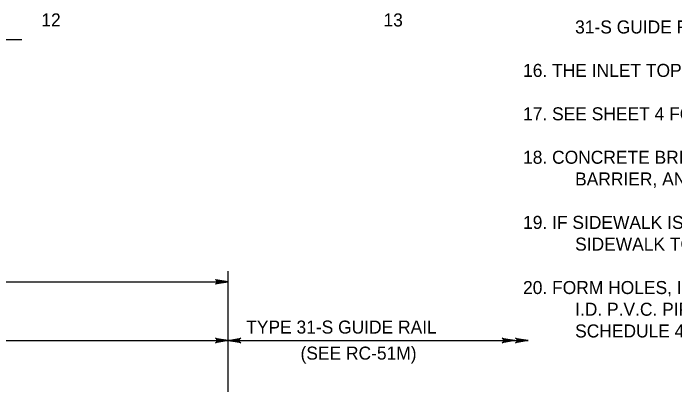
# Model space of a CAD drawing. Extents: x 632007860 to 635435983, y 295418622 to 297794622.
# Drawn here: x 632482682 to 632635172, y 297404858 to 297490406 of the extents above; entities that cross this region are included whole.
import ezdxf

# ---------------------------------------------------------------- set-up
doc = ezdxf.new("R2010")
doc.units = 0
for name, color, linetype in [('2', 7, 'Continuous'), ('S-DETL-DIMS', 7, 'Continuous'), ('S-DETL-T120', 7, 'Continuous')]:
    doc.layers.add(name, color=color, linetype=linetype)

msp = doc.modelspace()

# ---------------------------------------------------------------- linework, layer by layer
at = {"layer": '2'}
msp.add_line((632532195, 297350888), (632532195, 297431037), dxfattribs=at)
at = {"layer": 'S-DETL-DIMS'}
for p, q in [((632484648, 297484316), (632455117, 297484316)), ((632484648, 297484312), (632455117, 297484312)), ((632051871, 297428546), (632532195, 297428546)), ((632063630, 297415051), (632529656, 297415051)), ((632532195, 297415051), (632601381, 297415051))]:
    msp.add_line(p, q, dxfattribs=at)
for points in [[(632532195, 297428546), (632529282, 297428000), (632529395, 297428078), (632529507, 297428155), (632529565, 297428253), (632529623, 297428351), (632529639, 297428448), (632529656, 297428546), (632529639, 297428644), (632529623, 297428741), (632529565, 297428839), (632529507, 297428937), (632529395, 297429014), (632529282, 297429092), (632532195, 297428546), (632529395, 297429014), (632529507, 297428937), (632532195, 297428546), (632529565, 297428839), (632529623, 297428741), (632532195, 297428546), (632529639, 297428644), (632529656, 297428546), (632532195, 297428546), (632529639, 297428448), (632529623, 297428351), (632532195, 297428546), (632529565, 297428253), (632529507, 297428155), (632532195, 297428546), (632529395, 297428078)], [(632532195, 297415051), (632529282, 297414505), (632529507, 297414660), (632529623, 297414855), (632529656, 297415051), (632529623, 297415246), (632529507, 297415441), (632529282, 297415597), (632532195, 297415051), (632529507, 297415441), (632529623, 297415246), (632532195, 297415051), (632529656, 297415051), (632529623, 297414855), (632532195, 297415051), (632529507, 297414660)], [(632532195, 297415051), (632535108, 297415597), (632534883, 297415441), (632534767, 297415246), (632534734, 297415051), (632534767, 297414855), (632534883, 297414660), (632535108, 297414505), (632532195, 297415051), (632534883, 297414660), (632534767, 297414855), (632532195, 297415051), (632534734, 297415051), (632534767, 297415246), (632532195, 297415051), (632534883, 297415441)], [(632598281, 297415051), (632595368, 297414505), (632595593, 297414660), (632595709, 297414855), (632595742, 297415051), (632595709, 297415246), (632595593, 297415441), (632595368, 297415597), (632598281, 297415051), (632595593, 297415441), (632595709, 297415246), (632598281, 297415051), (632595742, 297415051), (632595709, 297414855), (632598281, 297415051), (632595593, 297414660)], [(632601381, 297415051), (632598468, 297414505), (632598693, 297414660), (632598808, 297414855), (632598842, 297415051), (632598808, 297415246), (632598693, 297415441), (632598468, 297415597), (632601381, 297415051), (632598693, 297415441), (632598808, 297415246), (632601381, 297415051), (632598842, 297415051), (632598808, 297414855), (632601381, 297415051), (632598693, 297414660)]]:
    msp.add_lwpolyline(points, dxfattribs=at)

# ---------------------------------------------------------------- texts
at = {"layer": 'S-DETL-T120'}
for s, height, p in [('12', 2999.8, (632489158, 297487362)), ('13', 2999.8, (632568032, 297487362)), ('31-S GUIDE RAIL.', 3000, (632612201, 297485746)), ('16. THE INLET TOP AND INLET BOX IS PERMITTED BETWEEN POSTS 1 & 2 OR 2 & 3.', 3000, (632600201, 297475746)), ('17. SEE SHEET 4 FOR SECTIONS A-A, B-B, C-C AND D-D.', 3000, (632600201, 297465746)), ('18. CONCRETE BRIDGE BARRIER SHOWN. PA TYPE 10M BRIDGE BARRIER, PA BRIDGE ', 3000, (632600201, 297455746)), ('BARRIER, AND PA 3-RAIL BRIDGE BARRIER SIMILAR.', 3000, (632612201, 297450746)), ('19. IF SIDEWALK IS PROVIDED, BARRIER HEIGHT IS MEASURED FROM THE TOP OF THE ', 3000, (632600201, 297440746)), ('SIDEWALK TO TOP OF THE BARRIER.', 3000, (632612201, 297435746)), ('20. FORM HOLES, IN THE CONCRETE, FOR THE 7/8" DIA. BOLTS WITH EITHER 1" ', 3000, (632600201, 297425746)), ('I.D. P.V.C. PIPE, SCHEDULE 40 OR 1" I.D. GALVANIZED STEEL PIPE, ', 3000, (632612201, 297420746)), ('TYPE 31-S GUIDE RAIL', 2999.85, (632536388, 297416640)), ('SCHEDULE 40.', 3000, (632612201, 297415746)), ('(SEE RC-51M)', 2999.85, (632548907, 297410641))]:
    msp.add_text(s, height=height, dxfattribs=at).set_placement(p)

doc.saveas('drawing.dxf')
